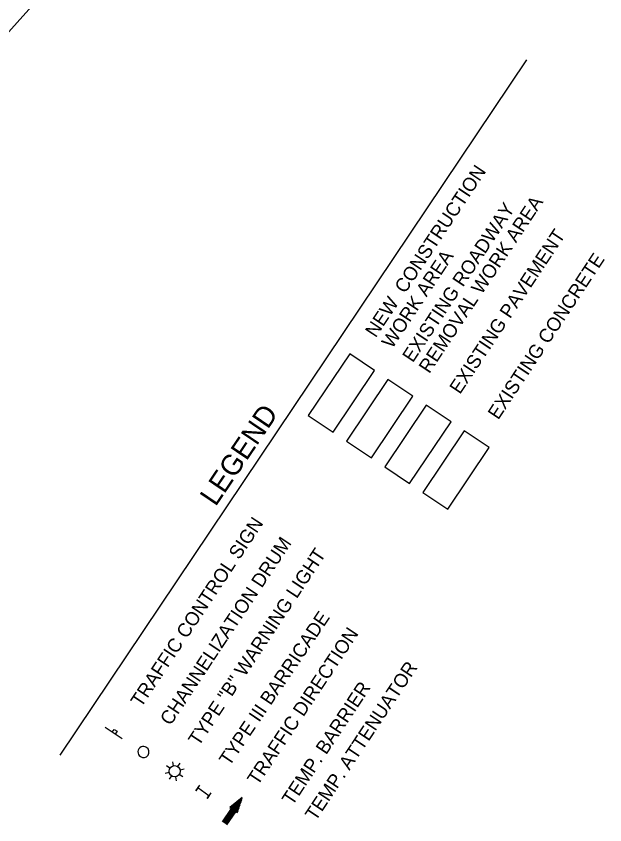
# Model space of a CAD drawing. Extents: x 1795987 to 1799689, y 243690 to 251545.
# Drawn here: x 1798565.9 to 1798900.7, y 248808.3 to 249268 of the extents above; entities that cross this region are included whole.
import ezdxf

# ---------------------------------------------------------------- set-up
doc = ezdxf.new("R2010")
doc.units = 0
for name, color, linetype in [('EP', 7, 'Continuous'), ('LEGEND', 7, 'Continuous'), ('Level 2', 7, 'Continuous'), ('Level 62', 7, 'Continuous'), ('Phase 2 Hatching', 7, 'Continuous')]:
    doc.layers.add(name, color=color, linetype=linetype)

msp = doc.modelspace()

# ---------------------------------------------------------------- linework, layer by layer
at = {"layer": 'EP'}
msp.add_lwpolyline([(1798216.89, 248917.03), (1798215.64, 248921.32), (1798215.98, 248921.6), (1798228.13, 248928.08), (1798240.09, 248934.92), (1798251.84, 248942.11), (1798263.38, 248949.63), (1798274.69, 248957.48), (1798285.77, 248965.66), (1798296.61, 248974.15), (1798307.2, 248982.96), (1798317.53, 248992.07), (1798327.59, 249001.48), (1798337.37, 249011.18), (1798345.46, 249019.64), (1798394.48, 249073.7), (1798463.65, 249150.34), (1798510.84, 249202.45), (1798571.52, 249269.95), (1798593.48, 249294.1), (1798640.54, 249345.86)], dxfattribs=at)
at = {"layer": 'LEGEND'}
for p, q in [((1798590.92, 248848), (1798856.3, 249243.25)), ((1798626.24, 248857.17), (1798616.52, 248863.69)), ((1798653.41, 248840.59), (1798651.49, 248841.88)), ((1798655.45, 248841.95), (1798655, 248844.22)), ((1798657.84, 248841.47), (1798659.13, 248843.38)), ((1798650.66, 248837.75), (1798652.93, 248838.2)), ((1798654.28, 248836.16), (1798653, 248834.24)), ((1798657.13, 248833.41), (1798656.68, 248835.68)), ((1798658.72, 248837.03), (1798660.63, 248835.74)), ((1798661.47, 248839.88), (1798659.2, 248839.43)), ((1798694.48, 248823.8), (1798687.51, 248818.11)), ((1798691.63, 248815.26), (1798694.48, 248823.8)), ((1798688.28, 248817.57), (1798683.12, 248810.1)), ((1798687.51, 248818.11), (1798688.28, 248817.57)), ((1798685.69, 248808.32), (1798690.85, 248815.8)), ((1798690.85, 248815.8), (1798691.63, 248815.26))]:
    msp.add_line(p, q, dxfattribs=at)
for points in [[(1798746.22, 249031.53), (1798769.78, 249066.62), (1798755.61, 249076.14), (1798732.05, 249041.04)], [(1798767.94, 249016.94), (1798791.51, 249052.04), (1798777.33, 249061.55), (1798753.77, 249026.46)], [(1798789.66, 249002.36), (1798813.23, 249037.45), (1798799.06, 249046.97), (1798775.49, 249011.87)], [(1798811.39, 248987.77), (1798834.95, 249022.87), (1798820.78, 249032.38), (1798797.21, 248997.29)], [(1798620.57, 248860.98), (1798621.66, 248862.6), (1798623.28, 248861.51), (1798622.19, 248859.89)]]:
    msp.add_lwpolyline(points, close=True, dxfattribs=at)
for points in [[(1798676.7, 248826.47), (1798674.47, 248823.27), (1798675.58, 248824.87), (1798669.18, 248829.32), (1798668.07, 248827.72), (1798670.3, 248830.92)], [(1798692.04, 248821.81), (1798683.68, 248809.71)], [(1798692.76, 248822.4), (1798683.9, 248809.56)], [(1798693.49, 248822.99), (1798684.11, 248809.41)], [(1798694.21, 248823.58), (1798684.33, 248809.27)], [(1798694.3, 248823.25), (1798684.54, 248809.12)], [(1798694, 248822.36), (1798684.75, 248808.97)], [(1798690.59, 248820.62), (1798683.26, 248810.01)], [(1798691.31, 248821.21), (1798683.47, 248809.86)], [(1798693.7, 248821.47), (1798684.97, 248808.82)], [(1798693.41, 248820.59), (1798685.18, 248808.68)], [(1798693.11, 248819.7), (1798685.39, 248808.53)], [(1798692.81, 248818.81), (1798685.61, 248808.38)], [(1798687.69, 248818.26), (1798687.56, 248818.07)], [(1798688.41, 248818.85), (1798687.77, 248817.92)], [(1798689.14, 248819.44), (1798687.99, 248817.77)], [(1798689.86, 248820.03), (1798688.2, 248817.63)], [(1798692.52, 248817.92), (1798690.98, 248815.7)], [(1798692.22, 248817.04), (1798691.2, 248815.56)], [(1798691.92, 248816.15), (1798691.41, 248815.41)]]:
    msp.add_lwpolyline(points, dxfattribs=at)
msp.add_circle((1798656.06, 248838.81), 3.19, dxfattribs=at)
for start, end in [(56.1222, 236.1222), (236.1222, 56.1222)]:
    msp.add_arc((1798638.35, 248849.73), 3.18, start, end, dxfattribs=at)
at = {"layer": 'Level 2'}
msp.add_lwpolyline([(1798811.39, 248987.77), (1798834.95, 249022.87), (1798820.78, 249032.38), (1798797.21, 248997.29)], close=True, dxfattribs=at)
at = {"layer": 'Level 62'}
msp.add_lwpolyline([(1798775.49, 249011.87), (1798789.66, 249002.36), (1798813.23, 249037.45), (1798799.06, 249046.97), (1798775.49, 249011.87)], dxfattribs=at)
at = {"layer": 'Phase 2 Hatching'}
msp.add_lwpolyline([(1798811.39, 248987.77), (1798834.95, 249022.87), (1798820.78, 249032.38), (1798797.21, 248997.29)], close=True, dxfattribs=at)

# ---------------------------------------------------------------- texts
at = {"layer": 'LEGEND'}
for s, height, rotation, p in [('NEW  CONSTRUCTION', 7.7999, 56.4352, (1798770.39, 249084.83)), ('EXISTING ROADWAY', 7.7999, 56.4352, (1798791.48, 249070.67)), ('REMOVAL WORK AREA', 7.7999, 56.4352, (1798800.84, 249064.45)), ('EXISTING PAVEMENT', 7.7999, 56.4352, (1798818.29, 249052.68)), ('WORK AREA', 7.8, 56.4352, (1798779.75, 249078.61)), ('EXISTING CONCRETE', 7.7999, 56.4352, (1798840.06, 249038.16)), ('LEGEND', 11.7, 55.9561, (1798679.36, 248988.86)), ('TRAFFIC CONTROL SIGN', 7.7999, 56.4352, (1798637, 248874.59)), ('CHANNELIZATION DRUM', 7.7999, 56.4352, (1798653.67, 248864.29)), ('TYPE "B" WARNING LIGHT', 7.7999, 56.4352, (1798669.75, 248852.6)), ('TYPE III BARRICADE', 7.7999, 55.9561, (1798687.23, 248841.23)), ('TRAFFIC DIRECTION', 7.7999, 56.4352, (1798703.3, 248830.24)), ('TEMP. ATTENUATOR', 7.7999, 56.4352, (1798736.19, 248810.01)), ('TEMP. BARRIER', 7.7999, 56.4352, (1798723.01, 248818.79))]:
    msp.add_text(s, height=height, rotation=rotation, dxfattribs=at).set_placement(p)

doc.saveas('drawing.dxf')
